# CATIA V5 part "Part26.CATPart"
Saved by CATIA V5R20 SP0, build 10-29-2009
Part number: socket countersunk head screw_din_DIN 7991 - M8 x 20 --- 20N
Revision: ANY
Definition: UNKNOWN
Nomenclature: socket countersunk head screw_din_DIN 7991 - M8 x 20 --- 20N
Source: Unknown
Bounding box of the stored display mesh (mm): x 0 to 20, y -7.59 to 7.59, z -7.785 to 7.785
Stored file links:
  C:\Users\Utente\Desktop\IO LAVORO\3D X SITO CF\CUMSA\3D files GR\GR 344038-15\Part26.CATPart
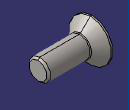
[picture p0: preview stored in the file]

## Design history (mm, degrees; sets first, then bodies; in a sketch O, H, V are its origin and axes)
Body1 "Hex" (main body)
  Solid1: solid without history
